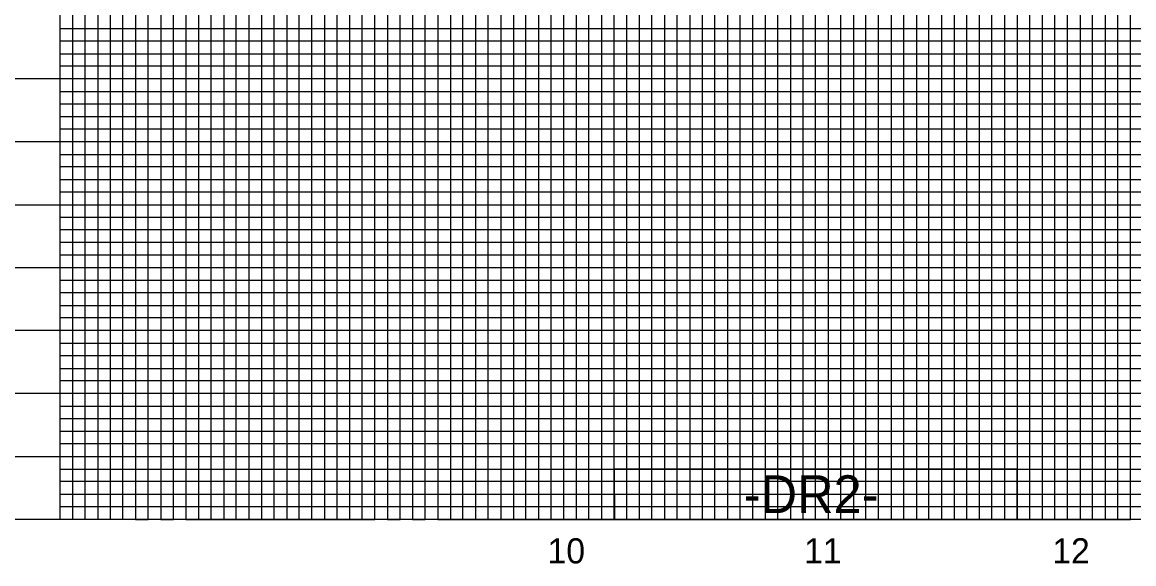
# Model space of a CAD drawing. Extents: x 1629787 to 1631995, y 1166253 to 1167353.
# Drawn here: x 1630739.3 to 1631180.6, y 1166810.8 to 1167025.9 of the extents above; entities that cross this region are included whole.
import ezdxf

# ---------------------------------------------------------------- set-up
doc = ezdxf.new("R2010")
doc.units = 0
for name, color, linetype in [('Exist Vertical Profile Horizontal Axis Label Major', 7, 'Continuous'), ('Prop Grid Mask', 7, 'Continuous'), ('Sheet Data Field CELL', 7, 'Continuous'), ('Sheet Layout Profile Border Port 1', 7, 'Continuous'), ('Sheet Profile CELL', 7, 'Continuous'), ('Sheet Profile Grid Major CELL', 7, 'Continuous'), ('Sheet Profile Grid Middle CELL', 7, 'Continuous'), ('Sheet Profile Grid Minor CELL', 7, 'Continuous')]:
    doc.layers.add(name, color=color, linetype=linetype)

msp = doc.modelspace()

# ---------------------------------------------------------------- linework, layer by layer
at = {"layer": 'Prop Grid Mask'}
msp.add_lwpolyline([(1630974.31, 1166848.4), (1631134.31, 1166848.4), (1631134.31, 1166828.4), (1630974.31, 1166828.4)], close=True, dxfattribs=at)
at = {"layer": 'Sheet Data Field CELL'}
msp.add_lwpolyline([(1630974.31, 1166828.4), (1631134.31, 1166828.4), (1631134.31, 1166848.4), (1630974.31, 1166848.4)], close=True, dxfattribs=at)
at = {"layer": 'Sheet Layout Profile Border Port 1'}
msp.add_lwpolyline([(1630754.31, 1167328.4), (1631054.21, 1167328.4), (1631054.31, 1167302.15), (1631254.26, 1167302.15), (1631254.31, 1167167.35), (1631404.31, 1167167.35), (1631404.31, 1166828.4), (1631134.31, 1166828.4), (1631134.31, 1166848.4), (1630974.31, 1166848.4), (1630974.46, 1166828.4), (1630754.31, 1166828.4)], close=True, dxfattribs=at)
at = {"layer": 'Sheet Profile CELL'}
msp.add_line((1631454.31, 1166828.4), (1629954.31, 1166828.4), dxfattribs=at)
at = {"layer": 'Sheet Profile Grid Major CELL'}
for p, q in [((1630754.31, 1166828.4), (1630754.31, 1167328.4)), ((1630804.31, 1167328.4), (1630804.31, 1166828.4)), ((1630854.31, 1166828.4), (1630854.31, 1167328.4)), ((1630904.31, 1167328.4), (1630904.31, 1166828.4)), ((1630954.31, 1166828.4), (1630954.31, 1167328.4)), ((1631004.31, 1167328.4), (1631004.31, 1166828.4)), ((1631054.31, 1166828.4), (1631054.31, 1167302.15)), ((1630804.31, 1166828.4), (1630854.31, 1166828.4)), ((1630904.31, 1166828.4), (1630954.31, 1166828.4)), ((1631004.31, 1166828.4), (1631054.31, 1166828.4))]:
    msp.add_line(p, q, dxfattribs=at)
for points in [[(1631104.31, 1167302.15), (1631104.31, 1166828.4), (1631154.31, 1166828.4), (1631154.31, 1167302.15)], [(1631454.31, 1167003.4), (1629954.31, 1167003.4), (1629954.31, 1166953.4), (1631454.31, 1166953.4)], [(1631454.31, 1166903.4), (1629954.31, 1166903.4), (1629954.31, 1166903.4), (1629954.31, 1166853.4), (1631454.31, 1166853.4)]]:
    msp.add_lwpolyline(points, dxfattribs=at)
at = {"layer": 'Sheet Profile Grid Middle CELL'}
for points in [[(1630779.31, 1166828.4), (1630779.31, 1167328.4), (1630829.31, 1167328.4), (1630829.31, 1166828.4), (1630879.31, 1166828.4), (1630879.31, 1167328.4), (1630929.31, 1167328.4), (1630929.31, 1166828.4), (1630979.31, 1166828.4), (1630979.31, 1167328.4), (1631029.31, 1167328.4), (1631029.31, 1166828.4), (1631079.31, 1166828.4), (1631079.31, 1167302.15)], [(1631129.31, 1167302.15), (1631129.31, 1166828.4), (1631179.31, 1166828.4)], [(1631179.31, 1166828.4), (1631179.31, 1167302.15)], [(1631454.31, 1166978.4), (1629954.31, 1166978.4), (1629954.31, 1166928.4), (1631454.31, 1166928.4)], [(1631454.31, 1166878.4), (1629954.31, 1166878.4)]]:
    msp.add_lwpolyline(points, dxfattribs=at)
at = {"layer": 'Sheet Profile Grid Minor CELL'}
for p, q in [((1630759.31, 1167328.4), (1630759.31, 1166828.4)), ((1630764.31, 1166828.4), (1630764.31, 1167328.4)), ((1630769.31, 1167328.4), (1630769.31, 1166828.4)), ((1630774.31, 1166828.4), (1630774.31, 1167328.4)), ((1630784.31, 1167328.4), (1630784.31, 1166828.4)), ((1630789.31, 1166828.4), (1630789.31, 1167328.4)), ((1630794.31, 1167328.4), (1630794.31, 1166828.4)), ((1630799.31, 1166828.4), (1630799.31, 1167328.4)), ((1630809.31, 1167328.4), (1630809.31, 1166828.4)), ((1630814.31, 1166828.4), (1630814.31, 1167328.4)), ((1630819.31, 1167328.4), (1630819.31, 1166828.4)), ((1630824.31, 1166828.4), (1630824.31, 1167328.4)), ((1630834.31, 1167328.4), (1630834.31, 1166828.4)), ((1630754.31, 1167023.4), (1631404.31, 1167023.4)), ((1631404.31, 1167018.4), (1630754.31, 1167018.4)), ((1630754.31, 1167013.4), (1631404.31, 1167013.4)), ((1631404.31, 1167008.4), (1630754.31, 1167008.4)), ((1630754.31, 1166998.4), (1631404.31, 1166998.4)), ((1631404.31, 1166993.4), (1630754.31, 1166993.4)), ((1630754.31, 1166988.4), (1631404.31, 1166988.4)), ((1631404.31, 1166983.4), (1630754.31, 1166983.4)), ((1630754.31, 1166973.4), (1631404.31, 1166973.4)), ((1631404.31, 1166968.4), (1630754.31, 1166968.4)), ((1630754.31, 1166963.4), (1631404.31, 1166963.4)), ((1631404.31, 1166958.4), (1630754.31, 1166958.4)), ((1630754.31, 1166948.4), (1631404.31, 1166948.4)), ((1631404.31, 1166943.4), (1630754.31, 1166943.4)), ((1631404.31, 1166938.4), (1630754.31, 1166938.4)), ((1631404.31, 1166933.4), (1630754.31, 1166933.4)), ((1630754.31, 1166923.4), (1631404.31, 1166923.4)), ((1631404.31, 1166918.4), (1630754.31, 1166918.4)), ((1630754.31, 1166913.4), (1631404.31, 1166913.4)), ((1631404.31, 1166908.4), (1630754.31, 1166908.4)), ((1630754.31, 1166898.4), (1631404.31, 1166898.4)), ((1631404.31, 1166893.4), (1630754.31, 1166893.4)), ((1630754.31, 1166888.4), (1631404.31, 1166888.4)), ((1631404.31, 1166883.4), (1630754.31, 1166883.4)), ((1630754.31, 1166873.4), (1631404.31, 1166873.4)), ((1631404.31, 1166868.4), (1630754.31, 1166868.4)), ((1630754.31, 1166863.4), (1631404.31, 1166863.4)), ((1631404.31, 1166858.4), (1630754.31, 1166858.4)), ((1630754.31, 1166848.4), (1631204.31, 1166848.4)), ((1631204.31, 1166843.4), (1630754.31, 1166843.4)), ((1630754.31, 1166838.4), (1631204.31, 1166838.4)), ((1630784.31, 1166828.4), (1630789.31, 1166828.4)), ((1630794.31, 1166828.4), (1630799.31, 1166828.4)), ((1630809.31, 1166828.4), (1630814.31, 1166828.4)), ((1630819.31, 1166828.4), (1630824.31, 1166828.4)), ((1630834.31, 1166828.4), (1630839.31, 1166828.4))]:
    msp.add_line(p, q, dxfattribs=at)
for points in [[(1630839.31, 1166828.4), (1630839.31, 1167328.4)], [(1630844.31, 1167328.4), (1630844.31, 1166828.4), (1630849.31, 1166828.4), (1630849.31, 1167328.4)], [(1630859.31, 1167328.4), (1630859.31, 1166828.4), (1630864.31, 1166828.4), (1630864.31, 1167328.4)], [(1630869.31, 1167328.4), (1630869.31, 1166828.4), (1630874.31, 1166828.4), (1630874.31, 1167328.4)], [(1630884.31, 1167328.4), (1630884.31, 1166828.4), (1630889.31, 1166828.4), (1630889.31, 1167328.4)], [(1630894.31, 1167328.4), (1630894.31, 1166828.4), (1630899.31, 1166828.4), (1630899.31, 1167328.4)], [(1630909.31, 1167328.4), (1630909.31, 1166828.4), (1630914.31, 1166828.4), (1630914.31, 1167328.4)], [(1630919.31, 1167328.4), (1630919.31, 1166828.4), (1630924.31, 1166828.4), (1630924.31, 1167328.4)], [(1630934.31, 1167328.4), (1630934.31, 1166828.4), (1630939.31, 1166828.4), (1630939.31, 1167328.4)], [(1630944.31, 1167328.4), (1630944.31, 1166828.4), (1630949.31, 1166828.4), (1630949.31, 1167328.4)], [(1630959.31, 1167328.4), (1630959.31, 1166828.4), (1630964.31, 1166828.4), (1630964.31, 1167328.4)], [(1630969.31, 1167328.4), (1630969.31, 1166828.4), (1630974.31, 1166828.4), (1630974.31, 1167328.4)], [(1630984.31, 1167328.4), (1630984.31, 1166828.4), (1630989.31, 1166828.4), (1630989.31, 1167328.4)], [(1630994.31, 1167328.4), (1630994.31, 1166828.4), (1630999.31, 1166828.4), (1630999.31, 1167328.4)], [(1631009.31, 1167328.4), (1631009.31, 1166828.4), (1631014.31, 1166828.4), (1631014.31, 1167328.4)], [(1631019.31, 1167328.4), (1631019.31, 1166828.4), (1631024.31, 1166828.4), (1631024.31, 1167328.4)], [(1631034.31, 1167328.4), (1631034.31, 1166828.4), (1631039.31, 1166828.4), (1631039.31, 1167328.4)], [(1631044.31, 1167328.4), (1631044.31, 1166828.4), (1631049.31, 1166828.4), (1631049.31, 1167328.4)], [(1631059.31, 1167302.15), (1631059.31, 1166828.4), (1631064.31, 1166828.4), (1631064.31, 1167302.15)], [(1631069.31, 1167302.15), (1631069.31, 1166828.4), (1631074.31, 1166828.4), (1631074.31, 1167302.15)], [(1631084.31, 1167302.15), (1631084.31, 1166828.4), (1631089.31, 1166828.4), (1631089.31, 1167302.15)], [(1631094.31, 1167302.15), (1631094.31, 1166828.4), (1631099.31, 1166828.4), (1631099.31, 1167302.15)], [(1631109.31, 1167302.15), (1631109.31, 1166828.4), (1631114.31, 1166828.4), (1631114.31, 1167302.15)], [(1631119.31, 1167302.15), (1631119.31, 1166828.4), (1631124.31, 1166828.4), (1631124.31, 1167302.15)], [(1631134.31, 1167302.15), (1631134.31, 1166828.4), (1631139.31, 1166828.4), (1631139.31, 1167302.15)], [(1631144.31, 1166828.4), (1631149.31, 1166828.4), (1631149.31, 1167302.15)], [(1631144.31, 1167302.15), (1631144.31, 1166828.4)], [(1631159.31, 1167302.15), (1631159.31, 1166828.4)], [(1631164.31, 1166828.4), (1631164.31, 1167302.15)], [(1631169.31, 1167302.15), (1631169.31, 1166828.4)], [(1631174.31, 1166828.4), (1631174.31, 1167302.15)], [(1631204.31, 1166833.4), (1630754.31, 1166833.4)]]:
    msp.add_lwpolyline(points, dxfattribs=at)

# ---------------------------------------------------------------- texts
at = {"layer": 'Exist Vertical Profile Horizontal Axis Label Major'}
for s, p in [('10', (1630947.9, 1166810.9)), ('11', (1631049.74, 1166810.9)), ('12', (1631148.29, 1166810.9))]:
    msp.add_text(s, height=10, dxfattribs=at).set_placement(p)
at = {"layer": 'Sheet Data Field CELL'}
msp.add_text('-DR2-', height=15, rotation=360, dxfattribs=at).set_placement((1631025.8, 1166830.9))

doc.saveas('drawing.dxf')
